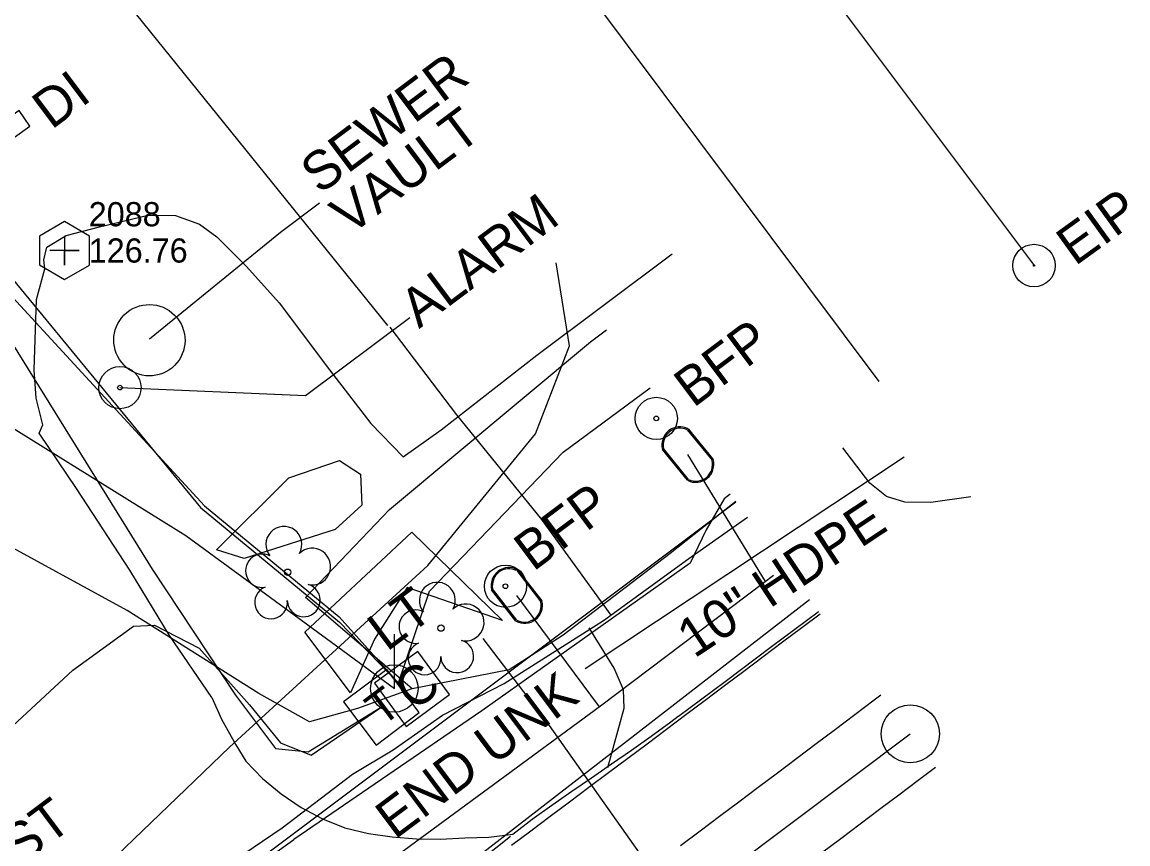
# Model space of a CAD drawing. Extents: x 2186615 to 2188822, y 629899 to 631820.
# Drawn here: x 2188429.1 to 2188543.3, y 631404.7 to 631489.6 of the extents above; entities that cross this region are included whole.
import ezdxf

# ---------------------------------------------------------------- set-up
doc = ezdxf.new("R2010")
doc.units = 0
for name, color, linetype in [('Exist Horizontal Alignment', 7, 'Continuous'), ('Exist Horizontal Alignment Point', 7, 'Continuous'), ('Exist Other Culture Area Outline', 7, 'Continuous'), ('Exist Other Culture Area Outline Leader', 7, 'Continuous'), ('Exist Other Culture Area Outline Text', 7, 'Continuous'), ('Exist Other Culture Located Object CELL', 7, 'Continuous'), ('Exist Other Culture Located Object Leader', 7, 'Continuous'), ('Exist Other Culture Located Object Text', 7, 'Continuous'), ('Exist Property Iron Pin CELL', 7, 'Continuous'), ('Exist Property Iron Pin Text', 7, 'Continuous'), ('Exist Property Line', 7, 'Continuous'), ('Exist Right of Way Easement Line', 7, 'Continuous'), ('Exist Right of Way Line', 7, 'Continuous'), ('Exist Roads EOP', 7, 'Continuous'), ('Exist Roads EOP Other', 7, 'Continuous'), ('Exist Roads EOP Text', 7, 'Continuous'), ('Exist Roads EOT', 7, 'Continuous'), ('Exist Roads Soil', 7, 'Continuous'), ('Exist Structure Minor Drop Inlet', 7, 'Continuous'), ('Exist Structure Minor Drop Inlet Text', 7, 'Continuous'), ('Exist Structure Minor Pipes HDPE 10 Inch', 7, 'Continuous'), ('Exist Structure Minor Pipes HDPE 10 Inch Text', 7, 'Continuous'), ('Exist Utilities Gas UG Line SUE LOS B', 7, 'Continuous'), ('Exist Utilities Other Located Object CELL', 7, 'Continuous'), ('Exist Utilities Other Located Object Text', 7, 'Continuous'), ('Exist Utilities Power Pole CELL', 7, 'Continuous'), ('Exist Utilities Power Pole Text', 7, 'Continuous'), ('Exist Utilities Power UG Cable SUE LOS B', 7, 'Continuous'), ('Exist Utilities Sanitary Sewer Clean-Out CELL', 7, 'Continuous'), ('Exist Utilities Sanitary Sewer Forced Main SUE LOS B', 7, 'Continuous'), ('Exist Utilities Sanitary Sewer Manhole Cogo Elevation', 7, 'Continuous'), ('Exist Utilities Sanitary Sewer Manhole Cogo Number', 7, 'Continuous'), ('Exist Utilities Telephone Pedestal CELL', 7, 'Continuous'), ('Exist Utilities Telephone UG Cable SUE LOS C', 7, 'Continuous'), ('Exist Utilities Telephone UG FO SUE LOS B', 7, 'Continuous'), ('Exist Utilities TV Pedestal CELL', 7, 'Continuous'), ('Exist Utilities TV UG Cable SUE LOS B', 7, 'Continuous'), ('Exist Utilities Water Meter CELL', 7, 'Continuous'), ('Exist Utilities Water UG Line SUE LOS B', 7, 'Continuous'), ('Exist Vegetation Hedge Row', 7, 'Continuous'), ('Exist Vegetation Tree CELL', 7, 'Continuous')]:
    doc.layers.add(name, color=color, linetype=linetype)

msp = doc.modelspace()

# ---------------------------------------------------------------- linework, layer by layer
at = {"layer": 'Exist Horizontal Alignment'}
msp.add_line((2187136.41, 630378.11), (2188520.86, 631416.04), dxfattribs=at)
at = {"layer": 'Exist Horizontal Alignment Point'}
msp.add_circle((2188520.86, 631416.04), 3, dxfattribs=at)
at = {"layer": 'Exist Other Culture Area Outline'}
msp.add_ellipse((2188442.24, 631456.71), major_axis=(2.32, -2.87), ratio=0.996367, dxfattribs=at)
at = {"layer": 'Exist Other Culture Area Outline Leader'}
msp.add_lwpolyline([(2188442.24, 631456.85), (2188455.77, 631467.86), (2188459.83, 631470.91)], dxfattribs=at)
at = {"layer": 'Exist Other Culture Located Object CELL'}
for radius in [2.18, 0.24]:
    msp.add_circle((2188439.2, 631451.81), radius, dxfattribs=at)
at = {"layer": 'Exist Other Culture Located Object Leader'}
msp.add_lwpolyline([(2188439.2, 631451.81), (2188458.37, 631450.99), (2188469.14, 631459.06)], dxfattribs=at)
at = {"layer": 'Exist Property Iron Pin CELL'}
for radius in [2.2, 0.0707]:
    msp.add_circle((2188533.64, 631464.42), radius, dxfattribs=at)
at = {"layer": 'Exist Property Line'}
msp.add_line((2188269.4, 631817.59), (2188533.64, 631464.42), dxfattribs=at)
at = {"layer": 'Exist Right of Way Easement Line'}
msp.add_line((2188259.84, 631796.98), (2188517.62, 631452.43), dxfattribs=at)
at = {"layer": 'Exist Right of Way Line'}
msp.add_line((2187118.41, 630402.11), (2188502.83, 631440.02), dxfattribs=at)
at = {"layer": 'Exist Roads EOP'}
for points in [[(2188496.92, 631417.87), (2188501.73, 631421.45), (2188506.53, 631425.05), (2188511.33, 631428.66), (2188511.36, 631428.68)], [(2188448.68, 631419.81), (2188449.7, 631417.54), (2188451.16, 631414.91), (2188452.22, 631413.23), (2188453.94, 631411.42), (2188455.87, 631409.85), (2188457.93, 631408.44), (2188460.13, 631407.27), (2188462.45, 631406.34), (2188464.87, 631405.74), (2188467.34, 631405.4), (2188469.83, 631405.19), (2188472.33, 631405.17), (2188474.83, 631405.28), (2188477.32, 631405.38), (2188479.8, 631405.69), (2188481.79, 631407.21), (2188483.81, 631408.68), (2188485.87, 631410.1), (2188487.93, 631411.51), (2188489.99, 631412.93), (2188492.04, 631414.36), (2188494.08, 631415.81), (2188496.1, 631417.28), (2188496.88, 631417.85)], [(2188407.73, 631351.93), (2188412.58, 631355.47), (2188417.43, 631359), (2188422.29, 631362.52), (2188427.16, 631366.03), (2188432.02, 631369.54), (2188436.84, 631373.11), (2188441.63, 631376.72), (2188446.43, 631380.33), (2188451.22, 631383.93), (2188456.02, 631387.53), (2188460.83, 631391.12), (2188465.64, 631394.71), (2188470.43, 631398.33), (2188475.18, 631402), (2188479.55, 631405.46)]]:
    msp.add_lwpolyline(points, dxfattribs=at)
at = {"layer": 'Exist Roads EOP Other'}
msp.add_lwpolyline([(2188448.68, 631419.81), (2188444.31, 631426.21), (2188440.22, 631432.96), (2188434.71, 631441.39), (2188430.84, 631447.12), (2188431.23, 631447.97), (2188430.53, 631450.72), (2188430.32, 631453.65), (2188430.59, 631460.92), (2188431.44, 631464.08), (2188431.33, 631465.03), (2188431.66, 631466.32), (2188433.64, 631467.54), (2188437.08, 631468.44), (2188442.12, 631469.62), (2188444.93, 631469.61), (2188447.43, 631468.7), (2188449.2, 631467.4), (2188452.29, 631464.32), (2188455.65, 631460.58), (2188460.85, 631453.66), (2188465.12, 631448.1), (2188468.45, 631444.66), (2188472.4, 631447.46), (2188482.26, 631455.17), (2188496.25, 631465.62)], dxfattribs=at)
at = {"layer": 'Exist Roads EOT'}
for points in [[(2188479.65, 631404.53), (2188481.65, 631406.03), (2188483.65, 631407.53), (2188485.65, 631409.03), (2188487.66, 631410.53), (2188489.66, 631412.03), (2188491.66, 631413.52), (2188493.66, 631415.02), (2188495.66, 631416.52), (2188497.66, 631418.03), (2188499.65, 631419.53), (2188501.65, 631421.03), (2188503.65, 631422.53), (2188505.65, 631424.03), (2188507.65, 631425.53), (2188509.65, 631427.04), (2188511.53, 631428.45)], [(2188497.13, 631404.51), (2188499.13, 631406.01), (2188501.13, 631407.52), (2188503.13, 631409.02), (2188505.13, 631410.52), (2188507.13, 631412.02), (2188509.12, 631413.53), (2188511.12, 631415.03), (2188513.12, 631416.53), (2188515.12, 631418.04), (2188517.11, 631419.54), (2188517.82, 631420.08)], [(2188511.68, 631403.74), (2188513.68, 631405.24), (2188515.68, 631406.74), (2188517.68, 631408.25), (2188519.68, 631409.75), (2188521.68, 631411.25), (2188523.46, 631412.58)]]:
    msp.add_lwpolyline(points, dxfattribs=at)
at = {"layer": 'Exist Roads Soil'}
for points in [[(2188527.11, 631440.54), (2188522.98, 631439.93), (2188520.28, 631439.99), (2188518.41, 631440.58), (2188516.68, 631441.95), (2188513.89, 631445.58)], [(2188489.61, 631412.57), (2188491.28, 631418.69), (2188491.23, 631420.58), (2188490.27, 631422.82), (2188487.68, 631427)]]:
    msp.add_lwpolyline(points, dxfattribs=at)
at = {"layer": 'Exist Structure Minor Drop Inlet'}
msp.add_lwpolyline([(2188428.77, 631480.43), (2188427.18, 631479.29), (2188428.29, 631477.69), (2188429.89, 631478.83), (2188428.77, 631480.43)], dxfattribs=at)
at = {"layer": 'Exist Structure Minor Pipes HDPE 10 Inch'}
msp.add_line((2188520.22, 631444.62), (2188487.27, 631422.77), dxfattribs=at)
at = {"layer": 'Exist Utilities Gas UG Line SUE LOS B'}
msp.add_line((2188429.17, 631504.88), (2188466.83, 631458.22), dxfattribs=at)
for points in [[(2188489.94, 631428.31), (2188482.8, 631438.17), (2188473.99, 631449.01), (2188467.13, 631458.07)], [(2188417.18, 631375.21), (2188429.81, 631386.38), (2188446.01, 631399.58), (2188455.97, 631406.32), (2188463.22, 631411.89), (2188467.43, 631414.38), (2188472.51, 631417.98), (2188478.88, 631421.23), (2188489.17, 631427.76), (2188497.99, 631434.15), (2188504.03, 631438.42)]]:
    msp.add_lwpolyline(points, dxfattribs=at)
at = {"layer": 'Exist Utilities Other Located Object CELL'}
for centre, radius in [((2188494.61, 631448.63), 2.18), ((2188494.61, 631448.63), 0.24), ((2188479.03, 631431.29), 2.18), ((2188479.03, 631431.29), 0.24)]:
    msp.add_circle(centre, radius, dxfattribs=at)
at = {"layer": 'Exist Utilities Power Pole CELL'}
for q in [(2188467.55, 631426.35), (2188467.55, 631420.73)]:
    msp.add_line((2188467.55, 631420.73), q, dxfattribs=at)
msp.add_circle((2188467.55, 631420.73), 2.45, dxfattribs=at)
at = {"layer": 'Exist Utilities Power UG Cable SUE LOS B'}
for points in [[(2188407.22, 631488.37), (2188447.53, 631439.43), (2188461.88, 631427.59), (2188468.04, 631421.22)], [(2188404.75, 631486.52), (2188447.95, 631439.61), (2188461.84, 631428.14), (2188468.04, 631421.22)], [(2188387.01, 631473.18), (2188446.02, 631436.55), (2188461.04, 631425.5), (2188467.55, 631420.73)], [(2188467.99, 631421.3), (2188471.18, 631430.79), (2188484.98, 631445.16), (2188493.99, 631451.78)]]:
    msp.add_lwpolyline(points, dxfattribs=at)
at = {"layer": 'Exist Utilities Sanitary Sewer Clean-Out CELL'}
msp.add_line((2188433.47, 631465.98), (2188433.47, 631465.98), dxfattribs=at)
msp.add_lwpolyline([(2188430.89, 631467.47), (2188430.89, 631464.49), (2188433.47, 631463), (2188436.05, 631464.48), (2188436.06, 631467.46), (2188433.48, 631468.96)], close=True, dxfattribs=at)
msp.add_lwpolyline([(2188433.47, 631467.49), (2188433.47, 631464.47), (2188433.47, 631465.98), (2188434.99, 631465.98), (2188431.96, 631465.98)], dxfattribs=at)
at = {"layer": 'Exist Utilities Sanitary Sewer Forced Main SUE LOS B'}
msp.add_lwpolyline([(2188476.69, 631425.88), (2188483.56, 631416.9), (2188496.5, 631398.59), (2188513.28, 631377.11)], dxfattribs=at)
at = {"layer": 'Exist Utilities Telephone Pedestal CELL'}
msp.add_line((2188466.14, 631418.76), (2188466.14, 631418.76), dxfattribs=at)
msp.add_lwpolyline([(2188465.66, 631414.87), (2188470.13, 631418.24), (2188466.76, 631422.7), (2188462.29, 631419.33), (2188465.66, 631414.87)], dxfattribs=at)
at = {"layer": 'Exist Utilities Telephone UG Cable SUE LOS C'}
for points in [[(2188407.88, 631488.87), (2188442.53, 631433.05), (2188451.14, 631420.04), (2188455.27, 631414.53), (2188458.64, 631414.17), (2188466.13, 631418.76)], [(2188450.5, 631414.66), (2188471, 631433.43), (2188482.15, 631447.03), (2188485.65, 631456.14), (2188484.26, 631464.72)], [(2188510.44, 631429.9), (2188476.35, 631403.47)], [(2188408.07, 631361.6), (2188411.32, 631370.46), (2188409.98, 631377.49), (2188402.34, 631391.62), (2188402.24, 631393.77), (2188411.88, 631401.83), (2188434.34, 631422.63), (2188440.61, 631427.17), (2188442.76, 631427.28), (2188447.4, 631424.9), (2188452.58, 631419.05), (2188455.8, 631415.11), (2188458.95, 631413.82), (2188466.14, 631418.76)], [(2188359.63, 631339.91), (2188390.14, 631363.91), (2188406.42, 631376.04), (2188429.82, 631394.77), (2188450.5, 631414.66)]]:
    msp.add_lwpolyline(points, dxfattribs=at)
at = {"layer": 'Exist Utilities Telephone UG FO SUE LOS B'}
for points in [[(2188502.23, 631440.82), (2188501.64, 631440.31), (2188499.75, 631437.11), (2188498.11, 631433.66), (2188476.58, 631418.41), (2188457.16, 631405.12)], [(2188303.07, 631290.83), (2188335.53, 631314.77), (2188356.73, 631330.39), (2188376.84, 631345.11), (2188395.22, 631359.35), (2188416.54, 631375.89), (2188457.16, 631405.12)]]:
    msp.add_lwpolyline(points, dxfattribs=at)
at = {"layer": 'Exist Utilities TV Pedestal CELL'}
msp.add_line((2188469.37, 631420.68), (2188469.37, 631420.68), dxfattribs=at)
msp.add_lwpolyline([(2188468.78, 631416.8), (2188473.25, 631420.09), (2188469.96, 631424.56), (2188465.49, 631421.26), (2188468.78, 631416.8)], dxfattribs=at)
at = {"layer": 'Exist Utilities TV UG Cable SUE LOS B'}
for points in [[(2188469.37, 631420.68), (2188463.75, 631418.67), (2188458.79, 631417.29), (2188453.55, 631420.22), (2188439.96, 631428.77), (2188375.11, 631464.23)], [(2188469.39, 631420.7), (2188458.38, 631430.12), (2188467.05, 631439.21), (2188487.81, 631456.55), (2188489.46, 631457.8)], [(2188502.82, 631440.03), (2188502.01, 631439.39), (2188496.05, 631434.66), (2188484.99, 631426.22), (2188479.41, 631422.64), (2188469.39, 631420.7)]]:
    msp.add_lwpolyline(points, dxfattribs=at)
at = {"layer": 'Exist Utilities Water Meter CELL'}
for p, q in [((2188497.88, 631444.89), (2188497.88, 631444.89)), ((2188480.2, 631430.34), (2188480.2, 631430.34))]:
    msp.add_line(p, q, dxfattribs=at)
for points in [[(2188497.81, 631447.46), (2188500.38, 631444.3)], [(2188497.91, 631447.54), (2188500.48, 631444.38)], [(2188497.85, 631442.24), (2188495.26, 631445.42)], [(2188497.95, 631442.32), (2188495.37, 631445.51)], [(2188480.19, 631432.9), (2188482.69, 631429.69)], [(2188480.29, 631432.99), (2188482.79, 631429.77)], [(2188480.11, 631427.68), (2188477.59, 631430.92)], [(2188480.22, 631427.77), (2188477.7, 631431.01)]]:
    msp.add_lwpolyline(points, dxfattribs=at)
for centre, radius, start, end in [((2188497.05, 631445.9), 1.86, 62.3023, 195.1037), ((2188497.06, 631445.89), 1.73, 64.4252, 192.9067), ((2188498.7, 631443.89), 1.86, 242.7726, 15.4327), ((2188498.7, 631443.88), 1.73, 244.2515, 13.9971), ((2188479.4, 631431.36), 1.86, 61.0335, 193.8349), ((2188479.4, 631431.36), 1.73, 63.1564, 191.6379), ((2188481, 631429.32), 1.86, 241.5038, 14.1639), ((2188481, 631429.31), 1.73, 242.9827, 12.7283)]:
    msp.add_arc(centre, radius, start, end, dxfattribs=at)
at = {"layer": 'Exist Utilities Water UG Line SUE LOS B'}
for p, q in [((2188505.89, 631431.78), (2188497.88, 631444.89)), ((2188488.76, 631418.84), (2188480.2, 631430.34))]:
    msp.add_line(p, q, dxfattribs=at)
msp.add_lwpolyline([(2188506.72, 631432.41), (2188505.72, 631431.65), (2188488.84, 631418.89), (2188462.18, 631399.29)], dxfattribs=at)
at = {"layer": 'Exist Vegetation Hedge Row'}
for points in [[(2188449.16, 631435.06), (2188456.65, 631442.49), (2188461.87, 631444.28), (2188464.05, 631442.87), (2188464.18, 631439.67), (2188461.42, 631437.17), (2188452.04, 631434.14), (2188449.16, 631435.06)], [(2188463.03, 631420.26), (2188458.29, 631426.55), (2188469.34, 631436.88), (2188478.71, 631427.75), (2188468.86, 631431.16), (2188465.49, 631425.81), (2188463.03, 631420.26)]]:
    msp.add_lwpolyline(points, dxfattribs=at)
at = {"layer": 'Exist Vegetation Tree CELL'}
for p, q in [((2188456.52, 631432.74), (2188456.52, 631432.74)), ((2188472.37, 631426.96), (2188472.37, 631426.96))]:
    msp.add_line(p, q, dxfattribs=at)
for centre in [(2188456.52, 631432.74), (2188472.37, 631426.96)]:
    msp.add_circle(centre, 0.326, dxfattribs=at)
for centre, radius, start, end in [((2188456.13, 631435.61), 1.86, 330.1651, 219.7134), ((2188459.06, 631433.32), 1.9, 257.1011, 134.1999), ((2188453.91, 631432.89), 1.73, 62.6636, 279.3457), ((2188458.19, 631429.84), 1.7, 181.2822, 74.56), ((2188471.99, 631429.84), 1.86, 330.1651, 219.7134), ((2188454.81, 631429.62), 1.69, 111.5671, 6.231), ((2188474.92, 631427.55), 1.9, 257.1011, 134.1999), ((2188469.77, 631427.12), 1.73, 62.6636, 279.3457), ((2188474.04, 631424.06), 1.7, 181.2822, 74.56), ((2188470.67, 631423.84), 1.69, 111.5671, 6.231)]:
    msp.add_arc(centre, radius, start, end, dxfattribs=at)

# ---------------------------------------------------------------- texts
at = {"layer": 'Exist Other Culture Area Outline Text'}
for s, p in [('SEWER', (2188459.85, 631471.71)), ('VAULT', (2188462.95, 631467.47))]:
    msp.add_text(s, height=4, rotation=36.8593, dxfattribs=at).set_placement(p)
at = {"layer": 'Exist Other Culture Located Object Text'}
msp.add_text('ALARM', height=4, rotation=36.8593, dxfattribs=at).set_placement((2188470.1, 631457.85))
at = {"layer": 'Exist Property Iron Pin Text'}
msp.add_text('EIP', height=4, rotation=35.7978, dxfattribs=at).set_placement((2188537.88, 631464.32))
at = {"layer": 'Exist Roads EOP Text'}
msp.add_text('BST', height=4, rotation=36.8593, dxfattribs=at).set_placement((2188426.13, 631400.22))
at = {"layer": 'Exist Structure Minor Drop Inlet Text'}
msp.add_text('DI', height=4, rotation=36.8593, dxfattribs=at).set_placement((2188432.13, 631478.4))
at = {"layer": 'Exist Structure Minor Pipes HDPE 10 Inch Text'}
for s, rotation, p in [('10" HDPE', 33.5458, (2188498.54, 631423.79)), ('END UNK', 36.8593, (2188467.6, 631405.05))]:
    msp.add_text(s, height=4, rotation=rotation, dxfattribs=at).set_placement(p)
at = {"layer": 'Exist Utilities Other Located Object Text'}
for p in [(2188498.44, 631449.66), (2188481.9, 631432.75)]:
    msp.add_text('BFP', height=4, rotation=36.8593, dxfattribs=at).set_placement(p)
at = {"layer": 'Exist Utilities Power Pole Text'}
msp.add_text('LT', height=4, rotation=36.8593, dxfattribs=at).set_placement((2188466.78, 631424.47))
at = {"layer": 'Exist Utilities Sanitary Sewer Manhole Cogo Elevation'}
msp.add_text('126.76', height=2.5, dxfattribs=at).set_placement((2188435.97, 631464.73))
at = {"layer": 'Exist Utilities Sanitary Sewer Manhole Cogo Number'}
msp.add_text('2088', height=2.5, dxfattribs=at).set_placement((2188435.97, 631468.48))
at = {"layer": 'Exist Utilities Telephone Pedestal CELL'}
msp.add_text('T', height=3.42, rotation=37.0392, dxfattribs=at).set_placement((2188466.26, 631416.72))
at = {"layer": 'Exist Utilities TV Pedestal CELL'}
msp.add_text('C', height=4, rotation=36.4036, dxfattribs=at).set_placement((2188469.5, 631418.29))

doc.saveas('drawing.dxf')
